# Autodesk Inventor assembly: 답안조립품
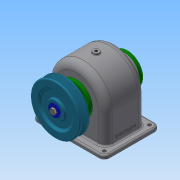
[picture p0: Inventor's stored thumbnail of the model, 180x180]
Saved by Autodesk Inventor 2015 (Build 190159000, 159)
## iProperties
Created: 2022-09
Part Number: 답안조립품
Document SubType Name: Assembly
Designer: 학생용
Author: 학생용
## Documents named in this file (16)
- C:\Users\학생용\Desktop\720906V1024\답안조립품.iam
- C:\Users\학생용\Desktop\720906V1024\본체.ipt
- C:\Users\학생용\Desktop\720906V1024\베어링 6203.ipt
- C:\Users\학생용\Desktop\720906V1024\뒤커버.ipt
- C:\Users\학생용\Desktop\720906V1024\축.ipt
- C:\Users\학생용\Desktop\720906V1024\키 6 x 6 x 22.ipt
- C:\Users\학생용\Desktop\720906V1024\스퍼기어.ipt
- C:\Users\학생용\Desktop\720906V1024\칼라.ipt
- C:\Users\학생용\Desktop\720906V1024\앞커버.ipt
- C:\Users\학생용\Desktop\720906V1024\오일 실 17 x 30 x 8.ipt
- C:\Users\학생용\Desktop\720906V1024\키 5 x 5 x 18.ipt
- C:\Users\학생용\Desktop\720906V1024\V-벨트풀리.ipt
- C:\Users\학생용\Desktop\720906V1024\멈춤나사 M4 x 10.ipt
- C:\Users\학생용\Desktop\720906V1024\와셔 6 x 22.ipt
- C:\Users\학생용\Desktop\720906V1024\육각머리볼트 M3 x 8.ipt
- C:\Users\학생용\Desktop\720906V1024\볼트 M3 x 10.ipt
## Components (9 placed, 2 different names)
1. V-벨트풀리:1
2. ISO 4762 M3 x 10:1
3. ISO 4762 M3 x 10:2
4. ISO 4762 M3 x 10:3
5. ISO 4762 M3 x 10:4
6. ISO 4762 M3 x 10:5
7. ISO 4762 M3 x 10:6
8. ISO 4762 M3 x 10:7
9. ISO 4762 M3 x 10:8
